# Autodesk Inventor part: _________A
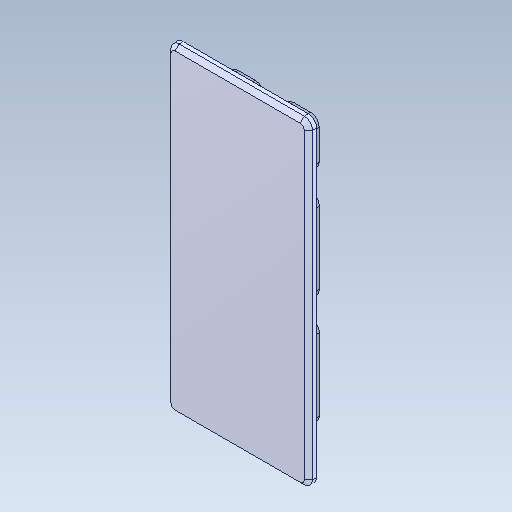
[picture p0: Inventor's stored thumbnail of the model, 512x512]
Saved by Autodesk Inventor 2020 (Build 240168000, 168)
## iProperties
Created: 2017-09
Part Number: _________A
Material: Générique
Document SubType Name: Modeling
Designer: bruno
Density: 1 g/cm^3
Appearance: Par défaut
Author: bruno
Sending System: SolidWorks 2016
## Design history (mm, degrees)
feature "Importée1"
node "Solide1"
